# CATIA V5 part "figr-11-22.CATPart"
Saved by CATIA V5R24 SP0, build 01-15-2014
Part number: Part1
Bounding box of the stored display mesh (mm): x -89.703 to 75.958, y -127.286 to 108.862, z -26.487 to 19.815
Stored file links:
  D:\KAVITA\CATIA V5-6R2014 Project_ Kavita\CATIA V5-6R2014_partfiles\Partfiles\c11_catia_v5-6r2014_prt\figr-11-22.CATPart
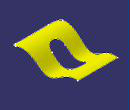
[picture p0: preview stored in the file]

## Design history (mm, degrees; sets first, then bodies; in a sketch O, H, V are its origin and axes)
Set1
  Extrude1: Element1 Sketch3, Lim1 86, Lim2 94, Direction yz-plane
  Sketch1 on xy-plane, origin (0, 0, 0), H (1, 0, 0), V (0, 1, 0)
    line L1 (64.3059, 108.8616) -> (75.9293, -106.0218)
    arc A1 centre (55.7837, -107.1115) radius 20.175 from (75.9293, -106.0218) to (55.7837, -127.2865) cw
    line L2 (55.7837, -127.2865) -> (-64.7868, -127.2865)
    arc A2 centre (-64.7868, -102.3613) radius 24.9252 from (-64.7868, -127.2865) to (-89.6873, -101.2501) cw
    line L3 (-89.6873, -101.2501) -> (-80.3115, 108.8616)
    line L4 (-80.3115, 108.8616) -> (64.3059, 108.8616)
    tangency: A1 L1, A2 L2, A2 L3, A1 L2
    horizontal: L2 H, L4 H
  Extrude2: Element1 Sketch1, Lim1 86, Lim2 94, Direction xy-plane
  Split1: ToCut Extrude1, Cutting Extrude2
  Sketch2 on xy-plane, origin (0, 0, 0), H (1, 0, 0), V (0, 1, 0)
    construction line L1 (-11.3849, 28.4134) -> (-11.3849, -36.9379)
    line L2 (12.8382, 28.4134) -> (12.8382, -36.9379)
    line L3 (-35.608, -36.9379) -> (-35.608, 28.4134)
    arc A1 centre (-11.3849, -36.9379) radius 24.2231 from (12.8382, -36.9379) to (-35.608, -36.9379) cw
    arc A2 centre (-11.3849, 28.4134) radius 24.2231 from (-35.608, 28.4134) to (12.8382, 28.4134) cw
    vertical: L1 V
    tangency: A1 L2, A2 L2, A1 L3, A2 L3
    parallelism: L1 L2
  Extrude3: Element1 Sketch2, Lim1 86, Lim2 94, Direction xy-plane
  Split2: ToCut Split1, Cutting Extrude3
  Boundary1: Boundary edge of Split2, Support Split2
Body1 (main body)
  Sketch3 on yz-plane, origin (0, 0, 0), H (0, 1, 0), V (0, 0, 1)
    spline S1 through (-130.9721, 0) (-85.5087, 19.8151) (-38.0512, 0) (0, -25.6483) (60.0541, -1.7202) (134.7951, -4.3868)
    point P1 (-130.9721, 0)
    point P2 (-38.0512, 0)
    point P3 (0, -25.6483)
    coincidence: P1 H, P2 H, P3 V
